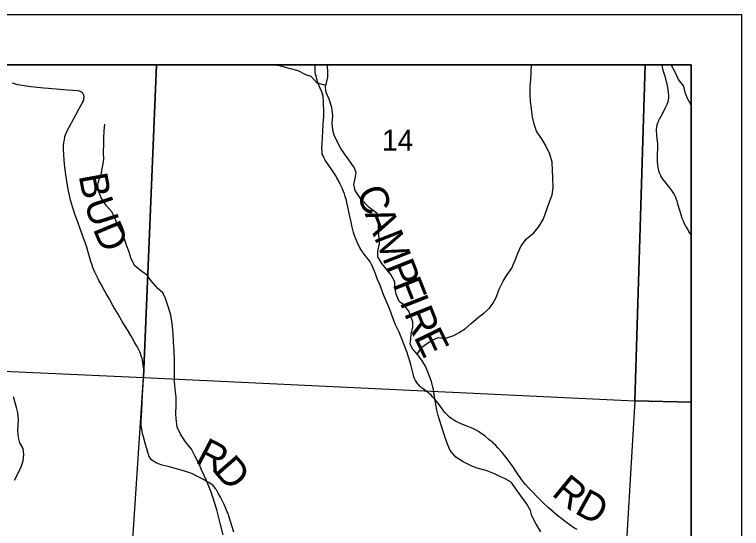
# Model space of a CAD drawing. Extents: x 0 to 34, y 0 to 22.
# Drawn here: x 29.474 to 30.917, y 19.979 to 21 of the extents above; entities that cross this region are included whole.
import ezdxf

# ---------------------------------------------------------------- set-up
doc = ezdxf.new("R2010")
doc.units = 0
for name, color, linetype in [('GM_X_Adjacent_County', 7, 'Continuous'), ('GM_X_County', 7, 'Continuous'), ('GM_X_Minor_River', 7, 'Continuous'), ('GM_X_Section', 7, 'Continuous'), ('GM_X_Section_Text', 7, 'Continuous'), ('GM_X_Township', 7, 'Continuous'), ('GM_X_Township_Road', 7, 'Continuous'), ('GM_X_Township_Road_Text', 7, 'Continuous'), ('SH_Data', 7, 'Continuous')]:
    doc.layers.add(name, color=color, linetype=linetype)

msp = doc.modelspace()

# ---------------------------------------------------------------- linework, layer by layer
at = {"layer": 'GM_X_Adjacent_County'}
msp.add_lwpolyline([(28.5181, 14.1), (30.8167, 14.1), (30.8167, 20.9), (28.7526, 20.9)], dxfattribs=at)
at = {"layer": 'GM_X_County'}
msp.add_lwpolyline([(28.5181, 14.1), (30.8167, 14.1), (30.8167, 20.9), (28.7526, 20.9)], dxfattribs=at)
at = {"layer": 'GM_X_Minor_River'}
for points in [[(30.092, 20.8593), (30.0741, 20.8637), (30.0627, 20.8768), (30.052, 20.8805), (30.0368, 20.888), (30.0213, 20.8924), (30.0114, 20.8945), (30, 20.8978), (29.9841, 20.8999), (29.9836, 20.9)], [(30.0955, 20.8859), (30.095, 20.8976), (30.0949, 20.9)], [(30.2728, 20.3254), (30.2819, 20.3397), (30.2917, 20.3458), (30.303, 20.3531), (30.3143, 20.3586), (30.3279, 20.3564), (30.3456, 20.3623), (30.3566, 20.3685), (30.369, 20.3765), (30.3802, 20.3865), (30.3949, 20.3988), (30.4054, 20.4072), (30.4163, 20.4168), (30.423, 20.4264), (30.4297, 20.4382), (30.436, 20.4549), (30.4434, 20.4705), (30.4498, 20.4804), (30.4606, 20.4965), (30.465, 20.5064), (30.4695, 20.5167), (30.4728, 20.5262), (30.4791, 20.541), (30.4899, 20.5548), (30.5046, 20.5663), (30.5154, 20.58), (30.524, 20.5945), (30.5277, 20.6055), (30.5351, 20.6261), (30.5406, 20.6417), (30.5427, 20.6557), (30.5422, 20.6754), (30.5416, 20.691), (30.5411, 20.7069), (30.5364, 20.7224), (30.5272, 20.7416), (30.521, 20.7518), (30.5099, 20.7687), (30.5052, 20.782), (30.5017, 20.7967), (30.4996, 20.813), (30.498, 20.827), (30.4971, 20.841), (30.4973, 20.8577), (30.4983, 20.8706), (30.4993, 20.8846), (30.4996, 20.8998), (30.4996, 20.9)], [(30.8167, 20.8208), (30.8148, 20.8237), (30.809, 20.8346), (30.8048, 20.8452), (30.802, 20.8577), (30.792, 20.8712), (30.7851, 20.8856), (30.7781, 20.8991), (30.7777, 20.9)], [(30.5184, 19.9725), (30.5088, 19.9891), (30.5007, 20.0042), (30.4976, 20.0151), (30.4899, 20.0287), (30.4784, 20.0441), (30.4677, 20.0603), (30.4592, 20.0716), (30.449, 20.0772), (30.4357, 20.0831), (30.4262, 20.0879), (30.4098, 20.0942), (30.392, 20.0993), (30.3817, 20.1034), (30.3639, 20.1119), (30.3494, 20.1213), (30.3387, 20.134), (30.3333, 20.1469), (30.3274, 20.1639), (30.3212, 20.1828), (30.3181, 20.193), (30.3149, 20.2039), (30.3122, 20.2145), (30.3098, 20.2262), (30.3074, 20.2406), (30.3054, 20.255), (30.3011, 20.2713), (30.2902, 20.3007), (30.2825, 20.3139), (30.2733, 20.3248), (30.2641, 20.3353), (30.2587, 20.3451), (30.2605, 20.3561), (30.2608, 20.3656), (30.2645, 20.3789), (30.264, 20.3895), (30.2601, 20.4005), (30.2562, 20.411), (30.2471, 20.4227), (30.2375, 20.4302), (30.231, 20.4449), (30.2286, 20.4585), (30.2288, 20.4695), (30.2208, 20.4835), (30.2028, 20.5053), (30.1951, 20.5188), (30.195, 20.5298), (30.1982, 20.5454), (30.1969, 20.5628), (30.1961, 20.573), (30.196, 20.5829), (30.1955, 20.5928), (30.1935, 20.6052), (30.1775, 20.6168), (30.1603, 20.6345), (30.1496, 20.6507), (30.1472, 20.6628), (30.1501, 20.6745), (30.1515, 20.6863), (30.1476, 20.6961), (30.1357, 20.7134), (30.1284, 20.7236), (30.1215, 20.7338), (30.1158, 20.744), (30.1084, 20.7602), (30.1057, 20.7704), (30.104, 20.784), (30.1054, 20.7988), (30.1034, 20.8155), (30.0979, 20.8317), (30.0925, 20.8453), (30.0912, 20.8559), (30.0956, 20.8757), (30.0955, 20.8859)], [(29.8876, 19.9666), (29.8828, 19.9874), (29.875, 20.0161), (29.8711, 20.0293), (29.8676, 20.0414), (29.8637, 20.0516), (29.8544, 20.0746), (29.8494, 20.0856), (29.8448, 20.0961), (29.8409, 20.106), (29.832, 20.1225), (29.8251, 20.1369), (29.8128, 20.1512), (29.8032, 20.1666), (29.7967, 20.1809), (29.7946, 20.1976), (29.7941, 20.2071), (29.7947, 20.2249), (29.7942, 20.2404), (29.7926, 20.2563), (29.7913, 20.2722), (29.7909, 20.3154), (29.7903, 20.3306), (29.7894, 20.3499), (29.7885, 20.367), (29.7868, 20.3863), (29.7836, 20.4029), (29.7789, 20.4199), (29.7735, 20.4362), (29.7677, 20.4471), (29.7581, 20.4561), (29.7448, 20.4711), (29.7363, 20.4828), (29.7268, 20.4888), (29.7127, 20.5011), (29.7054, 20.5147), (29.7011, 20.5279), (29.6953, 20.5438), (29.689, 20.5623), (29.6783, 20.5827), (29.6725, 20.5963), (29.6667, 20.6083), (29.656, 20.6204), (29.6456, 20.6358), (29.6405, 20.6498), (29.6393, 20.6626), (29.6415, 20.6725), (29.6455, 20.6832), (29.6484, 20.6972), (29.6509, 20.712), (29.65, 20.7276), (29.651, 20.742), (29.6509, 20.7545), (29.6519, 20.7693), (29.6526, 20.7822)], [(29.4733, 20.0754), (29.4819, 20.0918), (29.4867, 20.1021), (29.4907, 20.1135), (29.4921, 20.126), (29.4909, 20.1385), (29.4843, 20.1494), (29.4812, 20.16), (29.4803, 20.1733), (29.4816, 20.1953), (29.4804, 20.2089), (29.4776, 20.2195), (29.4714, 20.2406)]]:
    msp.add_lwpolyline(points, dxfattribs=at)
at = {"layer": 'GM_X_Section'}
for p, q in [((29.7552, 20.9), (28.7564, 20.9)), ((30.7256, 20.9), (29.7552, 20.9)), ((30.8167, 19.2109), (30.8167, 20.2305))]:
    msp.add_line(p, q, dxfattribs=at)
for points in [[(28.7564, 20.9), (28.7369, 20.296), (29.2336, 20.3016), (29.7299, 20.2792), (29.7552, 20.9)], [(29.7552, 20.9), (29.7299, 20.2792), (30.7049, 20.2326), (30.7256, 20.9)], [(30.7256, 20.9), (30.7049, 20.2326), (30.8167, 20.2305)], [(30.8167, 20.2305), (30.8167, 20.9), (30.7256, 20.9)], [(30.8167, 20.2305), (30.7049, 20.2326), (30.6447, 19.2173), (30.8167, 19.2109)]]:
    msp.add_lwpolyline(points, dxfattribs=at)
msp.add_lwpolyline([(30.7049, 20.2326), (30.6447, 19.2173), (29.6621, 19.2554), (29.7299, 20.2792)], close=True, dxfattribs=at)
at = {"layer": 'GM_X_Township'}
msp.add_lwpolyline([(30.8167, 18.1651), (30.8167, 20.9), (28.7526, 20.9)], dxfattribs=at)
at = {"layer": 'GM_X_Township_Road'}
for points in [[(30.5907, 19.9775), (30.5852, 19.9802), (30.5822, 19.9819), (30.5799, 19.9834), (30.5764, 19.986), (30.5692, 19.9915), (30.5604, 19.9984), (30.5531, 20.004), (30.5427, 20.0124), (30.5329, 20.021), (30.5221, 20.0313), (30.5124, 20.041), (30.5003, 20.0533), (30.4932, 20.0609), (30.4879, 20.0666), (30.4844, 20.0708), (30.4825, 20.0732), (30.4739, 20.0852), (30.4689, 20.0931), (30.4627, 20.1024), (30.4572, 20.11), (30.4487, 20.1213), (30.4415, 20.1301), (30.4333, 20.1397), (30.429, 20.1441), (30.424, 20.1489), (30.4228, 20.15), (30.416, 20.1557), (30.407, 20.1631), (30.3999, 20.1681), (30.3949, 20.1717), (30.3909, 20.1742), (30.3897, 20.1748), (30.3875, 20.1759), (30.3832, 20.1779), (30.3732, 20.182), (30.3618, 20.1863), (30.3544, 20.1896), (30.3492, 20.1922), (30.3454, 20.1944), (30.3417, 20.1969), (30.3374, 20.2004), (30.3319, 20.2056), (30.328, 20.2099), (30.3261, 20.2121), (30.3238, 20.215), (30.3163, 20.2253), (30.3137, 20.2288), (30.3078, 20.2363), (30.3035, 20.2411), (30.3004, 20.244), (30.298, 20.2461), (30.2951, 20.2486), (30.2932, 20.2502), (30.2876, 20.2544), (30.2827, 20.2579), (30.2815, 20.259), (30.2796, 20.2607), (30.2787, 20.2616), (30.275, 20.2657), (30.2723, 20.2692), (30.2698, 20.2735), (30.2678, 20.2771), (30.2664, 20.2806), (30.2654, 20.2836), (30.264, 20.2891), (30.2607, 20.3025), (30.2571, 20.316), (30.256, 20.3199), (30.2547, 20.3239), (30.2529, 20.3288), (30.2513, 20.3336), (30.2438, 20.3524), (30.237, 20.369), (30.2302, 20.3839), (30.2281, 20.3894), (30.2246, 20.3977), (30.2184, 20.4145), (30.2133, 20.4266), (30.2068, 20.4421), (30.1985, 20.4636), (30.1943, 20.4736), (30.188, 20.4906), (30.1858, 20.4964), (30.1842, 20.5001), (30.1824, 20.5036), (30.1794, 20.5089), (30.1763, 20.5134), (30.1699, 20.5215), (30.1661, 20.5263), (30.1625, 20.5314), (30.1599, 20.5353), (30.1582, 20.5385), (30.1558, 20.5436), (30.1524, 20.5514), (30.1493, 20.5594), (30.1466, 20.5669), (30.1437, 20.5777), (30.1416, 20.5879), (30.1386, 20.6024), (30.1354, 20.6183), (30.1335, 20.6269), (30.1326, 20.6306), (30.1303, 20.6385), (30.1284, 20.6439), (30.1266, 20.6487), (30.1238, 20.6551), (30.1199, 20.6631), (30.1172, 20.6689), (30.1155, 20.6724), (30.1137, 20.6756), (30.1126, 20.6777), (30.1037, 20.6913), (30.0905, 20.7108), (30.0874, 20.716), (30.0854, 20.7204), (30.0845, 20.723), (30.0842, 20.7261), (30.084, 20.7292), (30.0838, 20.7352), (30.084, 20.7436), (30.0855, 20.7675), (30.0865, 20.7831), (30.0874, 20.7976), (30.0879, 20.8093), (30.0873, 20.8229), (30.0868, 20.8299), (30.0865, 20.8341), (30.0861, 20.837), (30.0851, 20.8416), (30.0836, 20.8465), (30.0798, 20.8553), (30.0759, 20.8649), (30.0737, 20.8717), (30.0721, 20.8774), (30.0712, 20.8814), (30.0705, 20.8855), (30.0701, 20.891), (30.0701, 20.8996), (30.0701, 20.9)], [(30.7481, 20.7667), (30.748, 20.7677), (30.7479, 20.7719), (30.7484, 20.7763), (30.7496, 20.7811), (30.7508, 20.7847), (30.7524, 20.7892), (30.7536, 20.7921), (30.7544, 20.7936), (30.7571, 20.7983), (30.7634, 20.8097), (30.7667, 20.8166), (30.7694, 20.822), (30.7714, 20.8276), (30.7721, 20.8303), (30.7726, 20.8339), (30.7727, 20.8361), (30.7725, 20.8393), (30.7717, 20.8453), (30.7705, 20.8552), (30.7691, 20.8617), (30.768, 20.8666), (30.7649, 20.8773), (30.7638, 20.8808), (30.7624, 20.8852), (30.7609, 20.8914), (30.7594, 20.9)], [(29.7301, 20.2824), (29.7303, 20.2886), (29.73, 20.2953), (29.7296, 20.3), (29.7291, 20.3046), (29.7283, 20.309), (29.7274, 20.3139), (29.7262, 20.3186), (29.7251, 20.3223), (29.7236, 20.3269), (29.7221, 20.3301), (29.7189, 20.3368), (29.7155, 20.343), (29.7125, 20.3483), (29.7069, 20.3578), (29.7042, 20.3628), (29.6977, 20.3741), (29.6876, 20.3906), (29.6791, 20.4051), (29.6728, 20.4156), (29.6684, 20.4234), (29.6612, 20.4359), (29.6559, 20.4447), (29.6507, 20.454), (29.644, 20.4666), (29.6419, 20.4706), (29.6396, 20.4754), (29.636, 20.4828), (29.6333, 20.4882), (29.6312, 20.4928), (29.6294, 20.4976), (29.6276, 20.5025), (29.6254, 20.5098), (29.624, 20.5141), (29.6199, 20.5282), (29.617, 20.5378), (29.6146, 20.5453), (29.6102, 20.5582), (29.606, 20.5694), (29.5972, 20.5927), (29.5932, 20.6037), (29.5911, 20.6101), (29.5898, 20.614), (29.5886, 20.618), (29.586, 20.6271), (29.5849, 20.6315), (29.5834, 20.638), (29.5803, 20.6526), (29.5786, 20.6612), (29.5773, 20.6696), (29.5754, 20.6813), (29.5746, 20.6879), (29.5735, 20.6968), (29.5727, 20.7037), (29.5722, 20.7107), (29.5714, 20.7228), (29.5711, 20.7313), (29.571, 20.7348), (29.5711, 20.7385), (29.5715, 20.7456), (29.5726, 20.7515), (29.5738, 20.7577), (29.5761, 20.7641), (29.5789, 20.7706), (29.5821, 20.7766), (29.5853, 20.7825), (29.5873, 20.7861), (29.5945, 20.7995), (29.6014, 20.812), (29.608, 20.8241), (29.6096, 20.8275), (29.611, 20.8312), (29.6114, 20.8336), (29.6116, 20.8361), (29.6116, 20.837), (29.6114, 20.8386), (29.6109, 20.8403), (29.6101, 20.8419), (29.6092, 20.8436), (29.6077, 20.8452), (29.6069, 20.8458), (29.6058, 20.8465), (29.6042, 20.8472), (29.6024, 20.8478), (29.5987, 20.8484), (29.5893, 20.8493), (29.5782, 20.85), (29.5561, 20.8517), (29.548, 20.8523), (29.541, 20.8529), (29.5315, 20.8538), (29.5059, 20.8567), (29.4927, 20.8582), (29.4845, 20.8596), (29.4802, 20.8605), (29.4754, 20.8618), (29.4696, 20.8637)], [(30.8167, 20.5628), (30.8154, 20.5646), (30.8124, 20.5693), (30.8099, 20.5736), (30.8065, 20.5795), (30.8039, 20.5844), (30.8015, 20.5895), (30.7992, 20.5952), (30.7967, 20.6022), (30.7941, 20.6111), (30.7906, 20.6237), (30.7889, 20.6296), (30.7869, 20.635), (30.7862, 20.6369), (30.7844, 20.6406), (30.7823, 20.6445), (30.7812, 20.6465), (30.7784, 20.6507), (30.7743, 20.6561), (30.7644, 20.6681), (30.761, 20.6725), (30.7587, 20.6762), (30.7565, 20.68), (30.7557, 20.6815), (30.7544, 20.6843), (30.7539, 20.6857), (30.7529, 20.689), (30.7519, 20.6938), (30.7509, 20.7005), (30.7501, 20.7097), (30.7498, 20.7174), (30.7499, 20.7241), (30.7504, 20.7326), (30.7508, 20.7391), (30.7508, 20.7434), (30.7503, 20.7483), (30.7488, 20.7597), (30.7484, 20.7639), (30.7481, 20.7667)], [(29.9092, 19.972), (29.9064, 19.9804), (29.8989, 20.0041), (29.8974, 20.0088), (29.896, 20.0125), (29.8931, 20.019), (29.8895, 20.0271), (29.8822, 20.0417), (29.8781, 20.0497), (29.8745, 20.0558), (29.8729, 20.0584), (29.8709, 20.0611), (29.8692, 20.0629), (29.867, 20.0651), (29.8641, 20.0673), (29.8594, 20.0705), (29.8541, 20.0735), (29.8472, 20.0774), (29.8358, 20.0834), (29.827, 20.0879), (29.8198, 20.0905), (29.8064, 20.0947), (29.7903, 20.0991), (29.7785, 20.1023), (29.7666, 20.1054), (29.7596, 20.1077), (29.7548, 20.1098), (29.7527, 20.1108), (29.75, 20.1124), (29.7481, 20.1138), (29.7457, 20.1158), (29.7437, 20.1181), (29.7421, 20.1205), (29.7412, 20.1221), (29.7401, 20.1251), (29.7391, 20.1282), (29.7362, 20.1373), (29.7336, 20.1464), (29.7297, 20.1612), (29.7279, 20.1683), (29.7271, 20.1721), (29.7263, 20.1766), (29.7258, 20.18), (29.7253, 20.1853), (29.7253, 20.1926), (29.7262, 20.2136), (29.7279, 20.2438), (29.7291, 20.2654), (29.7299, 20.2757), (29.73, 20.2805), (29.7301, 20.2824)]]:
    msp.add_lwpolyline(points, dxfattribs=at)
at = {"layer": 'SH_Data'}
for points in [[(23.9167, 21), (30.9167, 21), (30.9167, 14), (23.9167, 14)], [(24.0167, 20.9), (30.8167, 20.9), (30.8167, 14.1), (24.0167, 14.1)]]:
    msp.add_lwpolyline(points, close=True, dxfattribs=at)

# ---------------------------------------------------------------- texts
at = {"layer": 'GM_X_Section_Text'}
msp.add_text('14', height=0.04186, rotation=0, dxfattribs=at).set_placement((30.203, 20.7296))
at = {"layer": 'GM_X_Township_Road_Text'}
for s, rotation, p in [('B', 280.4473, (29.6009, 20.6803)), ('C', 291.5108, (30.1514, 20.6479)), ('U', 288.1018, (29.6113, 20.6265)), ('A', 291.5104, (30.1685, 20.6045)), ('D', 292.6222, (29.6285, 20.5745)), ('M', 291.5074, (30.1868, 20.558)), ('P', 291.5128, (30.2094, 20.5006)), ('F', 291.512, (30.2235, 20.4649)), ('I', 291.5072, (30.2375, 20.4293)), ('R', 291.8743, (30.2462, 20.4072)), ('E', 295.816, (30.2654, 20.36)), ('R', 332.3702, (29.8302, 20.111)), ('D', 311.1023, (29.8672, 20.0928)), ('R', 320.6447, (30.5379, 20.0467)), ('D', 331.1661, (30.5833, 20.0108))]:
    msp.add_text(s, height=0.0568, rotation=rotation, dxfattribs=at).set_placement(p)

doc.saveas('drawing.dxf')
